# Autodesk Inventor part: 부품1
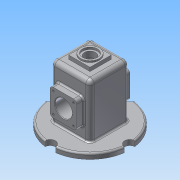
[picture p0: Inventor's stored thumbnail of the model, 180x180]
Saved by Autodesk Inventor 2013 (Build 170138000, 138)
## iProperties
Created: 2018-07
Part Number: 부품1
Material: 알루미늄 6061
Document SubType Name: Modeling
Designer: Administrator
Mass: 1013.28 g
Surface Area: 1076.76 cm^2
Volume: 373.903 cm^3
Density: 2.71 g/cm^3
Author: Administrator
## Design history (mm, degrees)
sketch "스케치1"
  geometry: L1 (-37, -37)-(37, -37); L2 (37, -37)-(37, 37); L3 (37, 37)-(-37, 37); L4 (-37, 37)-(-37, -37); L5 (-37, -37)-(37, 37); L6 (37, -37)-(-37, 37); 1 further point
  constraints: 12 end point, 2 midpoint, 2 parallel, 1 horizontal, 1 perpendicular
  dimensions: "d0" = 74 distance of L2.end L3.end; "d2" = 74 distance of L3.end L1.start
extrude "돌출1" new body sketch "스케치1" distance "d3" = 110; taper "d4" = 0 deg
sketch "스케치2"
  geometry: L1 (-32, -32)-(32, -32); L2 (32, -32)-(32, 32); L3 (32, 32)-(-32, 32); L4 (-32, 32)-(-32, -32); L5 (-32, -32)-(32, 32); L6 (32, -32)-(-32, 32); 1 further point
  constraints: 12 end point, 2 midpoint, 2 parallel, 1 horizontal, 1 perpendicular
  dimensions: "d5" = 64 distance of L2.end L3.end; "d7" = 64 distance between parallel lines of L1 L3
extrude "돌출2" cut sketch "스케치2" distance "d8" = 105; taper "d9" = 0 deg
node "작업 평면1"
sketch "스케치3"
  geometry: L1 (-25, 80)-(25, 80); L2 (25, 80)-(25, 30); L3 (25, 30)-(-25, 30); L4 (-25, 30)-(-25, 80); L5 (-37, 0)-(37, 0) reference; 4 further points
  constraints: 8 end point, 3 midpoint, 2 parallel, 2 vertical alignment, 1 horizontal, 1 perpendicular
  dimensions: "d11" = 50 distance of L1.start L1.end; "d13" = 50 distance of L3.end L1.start; "d14" = 30 distance between parallel lines of L5 L3
extrude "돌출3" join sketch "스케치3" stored distance "d15" = 105; taper "d16" = 0 deg
fillet "모깎기1" dims "d22" = 6
sketch "스케치5"
  geometry: A1 r 6 centre (-19, 36) between (-25, 36) and (-19, 30) reference; A2 r 6 centre (19, 36) between (19, 30) and (25, 36) reference; A3 r 6 centre (19, 74) between (25, 74) and (19, 80) reference; A4 r 6 centre (-19, 74) between (-19, 80) and (-25, 74) reference; 5 further points
  constraints: 4 coincident
hole "구멍1" sketch "스케치5" at (-19, 74), (-19, 36), (19, 36), (19, 74) diameter "d23" = 3.459; stored, may be unused: countersink angle "d27" = 90 deg, drill point angle "d29" = 118 deg; dims "d24" = 8, "d25" = 4, "d26" = 2, "d28" = 10
fillet "모깎기2" dims "d33" = 8
fillet "모깎기3" dims "d34" = 3
fillet "모깎기4" dims "d35" = 3
sketch "스케치6"
  geometry: L1 (32.548, 25)-(30, 32); L2 (102, 32)-(0, 32) reference; L3 (0, 32)-(0, 29) reference; L4 (32.548, 25)-(55, 25); L5 (72, 50)-(38, 50) reference; L6 (55, 50)-(55, 25); L7 (55, 50)-(30, 50); L8 (30, 50)-(30, 32); 1 further point
  constraints: 10 end point, 3 perpendicular, 2 point on line, 1 midpoint
  dimensions: "d36" = 110 deg angle of L1 L2; "d37" = 30 distance from line of L3 L1.end; "d38" = 7 distance between parallel lines of L2 L4
revolve "회전1" sketch "스케치6" stored, may be unused: angle "d39" = 90 deg
fillet "모깎기5" dims "d40" = 6
fillet "모깎기6" dims "d41" = 3
sketch "스케치7"
  geometry: A1 r 6 centre (38, -6) between (44, -6) and (38, 0) reference; A2 r 6 centre (0, -6) between (0, 0) and (-6, -6) reference; A3 r 6 centre (0, -44) between (-6, -44) and (0, -50) reference; 5 further points
  constraints: 3 coincident
hole "구멍2" sketch "스케치7" at (0, -6), (0, -44), (38, -41.96), (38, -6) diameter "d42" = 3.459; stored, may be unused: countersink angle "d46" = 90 deg, drill point angle "d48" = 118 deg; dims "d43" = 8, "d44" = 4, "d45" = 2, "d47" = 10
sketch "스케치8"
  geometry: L1 (-29, 0)-(29, 0) reference; L2 (-29, 110)-(29, 110) reference; C1 r 16 at (0, 55); 2 further points
  constraints: 1 centre point, 1 midpoint, 1 vertical alignment
  dimensions: "d49" = 55 distance from line of L1 C1.centre; "d50" = 32 diameter of C1
extrude "돌출5" cut sketch "스케치8" stored distance "d51" = 105; taper "d52" = 0 deg
chamfer "모따기2" distance "d53" = 1; stored, may be unused: second distance "d54" = 2, angle "d55" = 45 deg
chamfer "모따기3" distance "d56" = 1; stored, may be unused: second distance "d57" = 2, angle "d58" = 45 deg
fillet "모깎기7" dims "d59" = 8
sketch "스케치9"
  geometry: C1 r 75 at (0, 0); 1 further point
  constraints: 1 centre point, 1 coincident
  dimensions: "d60" = 150 diameter of C1
extrude "돌출6" join sketch "스케치9" distance "d62" = 10; taper "d63" = 0 deg
fillet "모깎기8" dims "d64" = 3
fillet "모깎기9" dims "d65" = 3
sketch "스케치10"
  geometry: C1 r 72 at (0, 0) reference; C2 r 10 at (0, 75); 1 further point
  constraints: 2 vertical alignment, 1 centre point, 1 other
  dimensions: "d66" = 20 diameter of C2
extrude "돌출7" cut sketch "스케치10" distance "d68" = 10; taper "d69" = 0 deg
fillet "모깎기10" dims "d73" = 3
sketch "스케치11"
  geometry: L1 (0, 0)-(58, 0) reference; L2 (38.978, -102)-(103.333, -102) reference; 3 further points
  constraints: 1 midpoint, 1 vertical alignment, 1 other
  dimensions: "d91" = 90 distance from line of L2 point (29, -12)
sketch "스케치12"
  geometry: L1 (-20, -20)-(20, -20); L2 (20, -20)-(20, 20); L3 (20, 20)-(-20, 20); L4 (-20, 20)-(-20, -20); L5 (-20, -20)-(20, 20); L6 (20, -20)-(-20, 20); 1 further point
  constraints: 12 end point, 2 midpoint, 2 parallel, 1 horizontal, 1 perpendicular
  dimensions: "d74" = 40 distance of L1.end L2.end; "d76" = 40 distance of L1.start L1.end
extrude "돌출8" join sketch "스케치12" distance "d77" = 7; taper "d78" = 0 deg
sketch "스케치13"
  geometry: C1 r 17.5 at (0, 0); 1 further point
  constraints: 1 centre point, 1 coincident
  dimensions: "d79" = 35 diameter of C1
extrude "돌출9" join sketch "스케치13" distance "d81" = 3; taper "d82" = 0 deg
sketch "스케치14"
  geometry: C1 r 17.5 at (0, 0) reference; C2 r 14 at (0, 0)
  constraints: 1 centre point, 1 coincident
  dimensions: "d83" = 28 diameter of C2
extrude "돌출10" cut sketch "스케치14" distance "d85" = 4; taper "d86" = 0 deg
sketch "스케치15"
  geometry: C1 r 14 at (0, 0) reference; C2 r 10.5 at (0, 0)
  constraints: 1 centre point, 1 coincident
  dimensions: "d87" = 21 diameter of C2
extrude "돌출11" cut sketch "스케치15" stored distance "d89" = 4; taper "d90" = 0 deg
feature "엠보싱1" dims "d11" = 50, "d13" = 50, "d14" = 30, "d92" = 0.5, "d93" = 0
sketch "스케치16"
  geometry: L1 (-32, -32)-(32, -32); L2 (32, -32)-(32, 32); L3 (32, 32)-(-32, 32); L4 (-32, 32)-(-32, -32); L5 (-32, -32)-(32, 32); L6 (32, -32)-(-32, 32); C1 r 10.5 at (0, 0) reference; A1 r 75 centre (0, 0) between (9.978, -74.333) and (74.333, -9.978) reference
  constraints: 12 end point, 2 midpoint, 2 parallel, 1 horizontal, 1 perpendicular
  dimensions: "d94" = 64 distance of L2.end L3.end; "d96" = 64 distance of L3.end L1.start
extrude "돌출12" cut sketch "스케치16" distance "d97" = 10; taper "d98" = 0 deg
node "솔리드1"
mirror "대칭1"
pattern_circular "원형 패턴1" dims angle "d71" = 360 deg
